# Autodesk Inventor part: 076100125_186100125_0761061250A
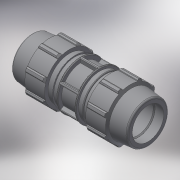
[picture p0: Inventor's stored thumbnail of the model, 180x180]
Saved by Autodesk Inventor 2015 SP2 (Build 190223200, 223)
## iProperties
Created: 2017-02
Part Number: 076100125_186100125_0761061250A
Material: Generic
Description: PLASSON REPAIR COUPLER 125
Document SubType Name: Modeling
Designer: KIM
Mass: 6064.09 g
Surface Area: 5423.74 cm^2
Volume: 6064.09 cm^3
Density: 1 g/cm^3
Appearance: Default
Author: KIM
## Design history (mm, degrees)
derived "07610.ipt"
feature "Solid1::07610.ipt"
tag "TaggingFeature1"
body "Solid1"
other parameters: "d2" = 125, "d4" = 38.33333, "d5" = 65.71429, "d7" = 212, "d8" = 159, "d9" = 65.71429, "d11" = 3.48571, "d12" = 169.6, "d13" = 120 deg, "d14" = 162.5, "d15" = 6 deg, "d16" = 190.8, "d18" = 6.25, "d19" = 35 deg, "d20" = 17.5 deg, "d21" = 197.16, "d23" = 0, "d25" = 360 deg, "d27" = 4.24, "d33" = 2.5, "d34" = 10.6, "d36" = 0, "d37" = 2.5, "d38" = 2.5, "d40" = 360 deg, "d42" = 82.8, "d43" = 6.36, "d46" = 3.75, "d50" = 19.28571, "d51" = 169.6, "d_" = 125, "E_" = 212, "l_" = 265, "d49" = 42.05714
